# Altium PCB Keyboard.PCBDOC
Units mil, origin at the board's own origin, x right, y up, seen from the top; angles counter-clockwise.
Board outline 6000 x 4000 mil, 2 copper layers (Top Layer, Bottom Layer); 17 components, 8 nets, 40 pads, 0 vias.
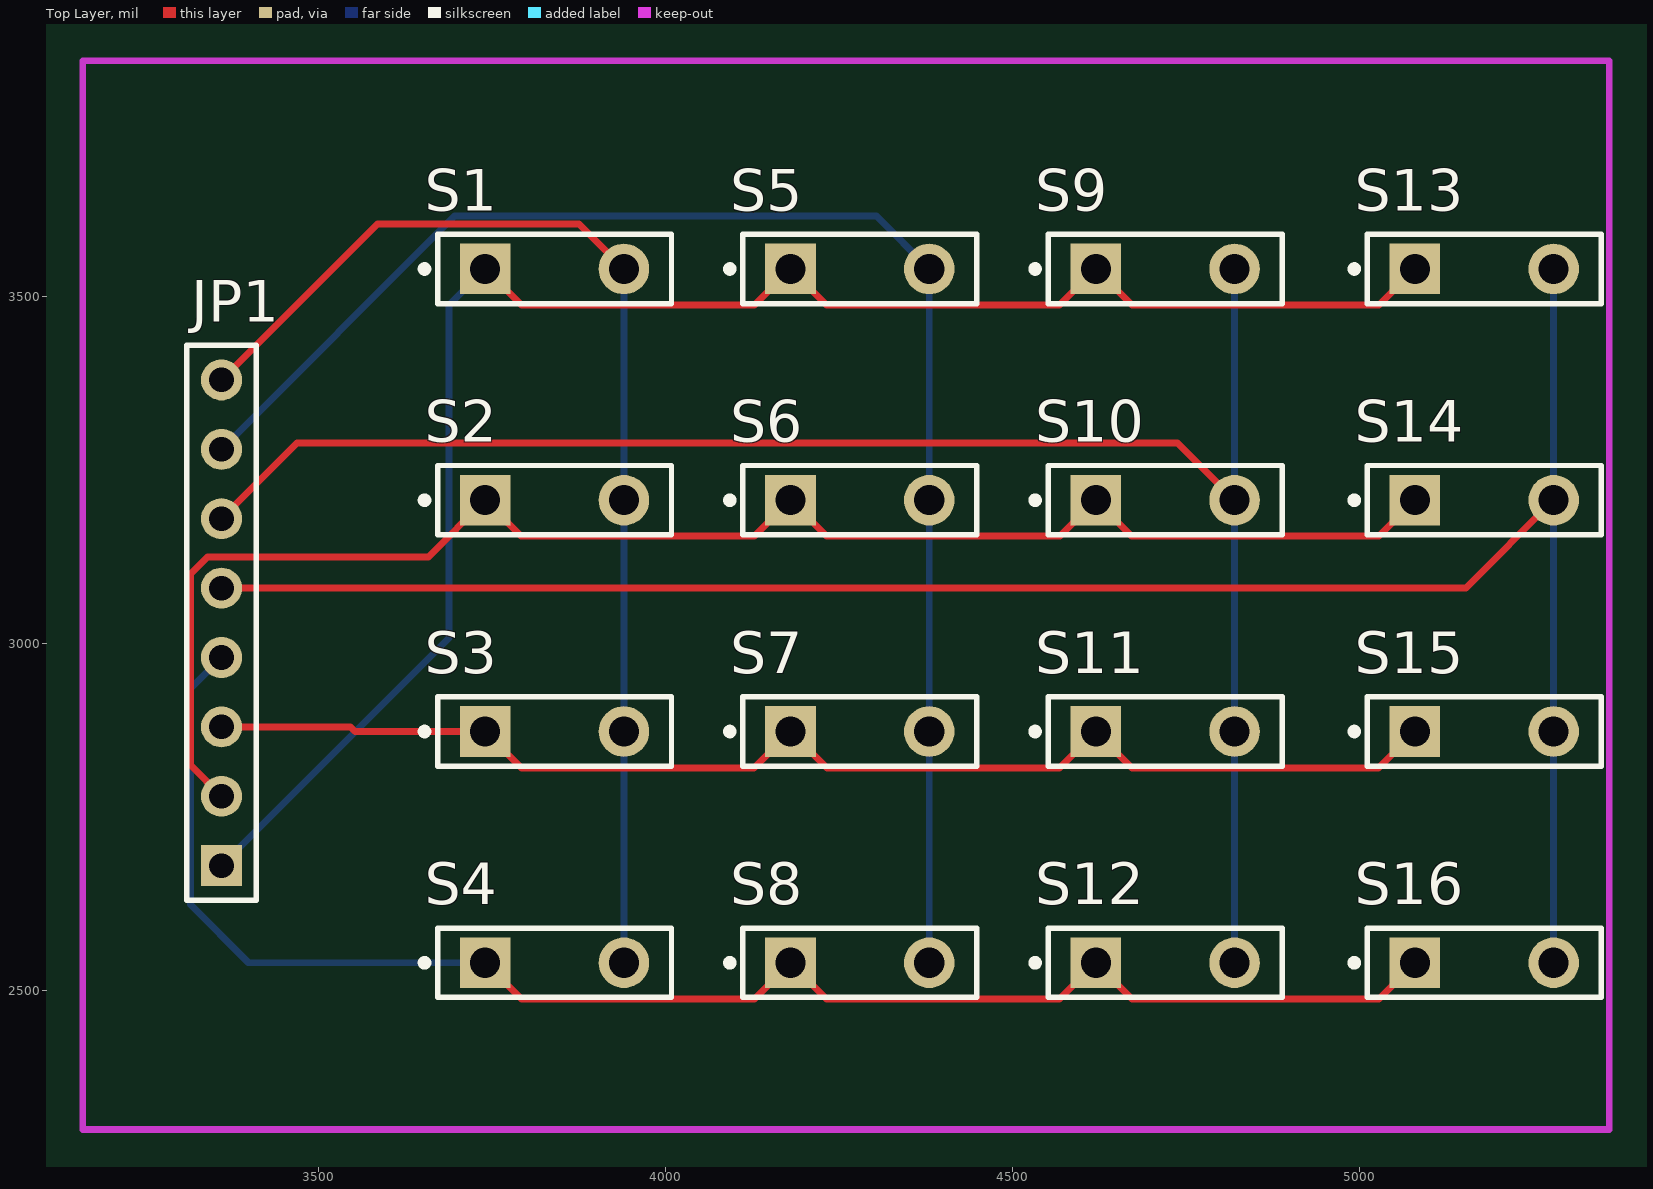
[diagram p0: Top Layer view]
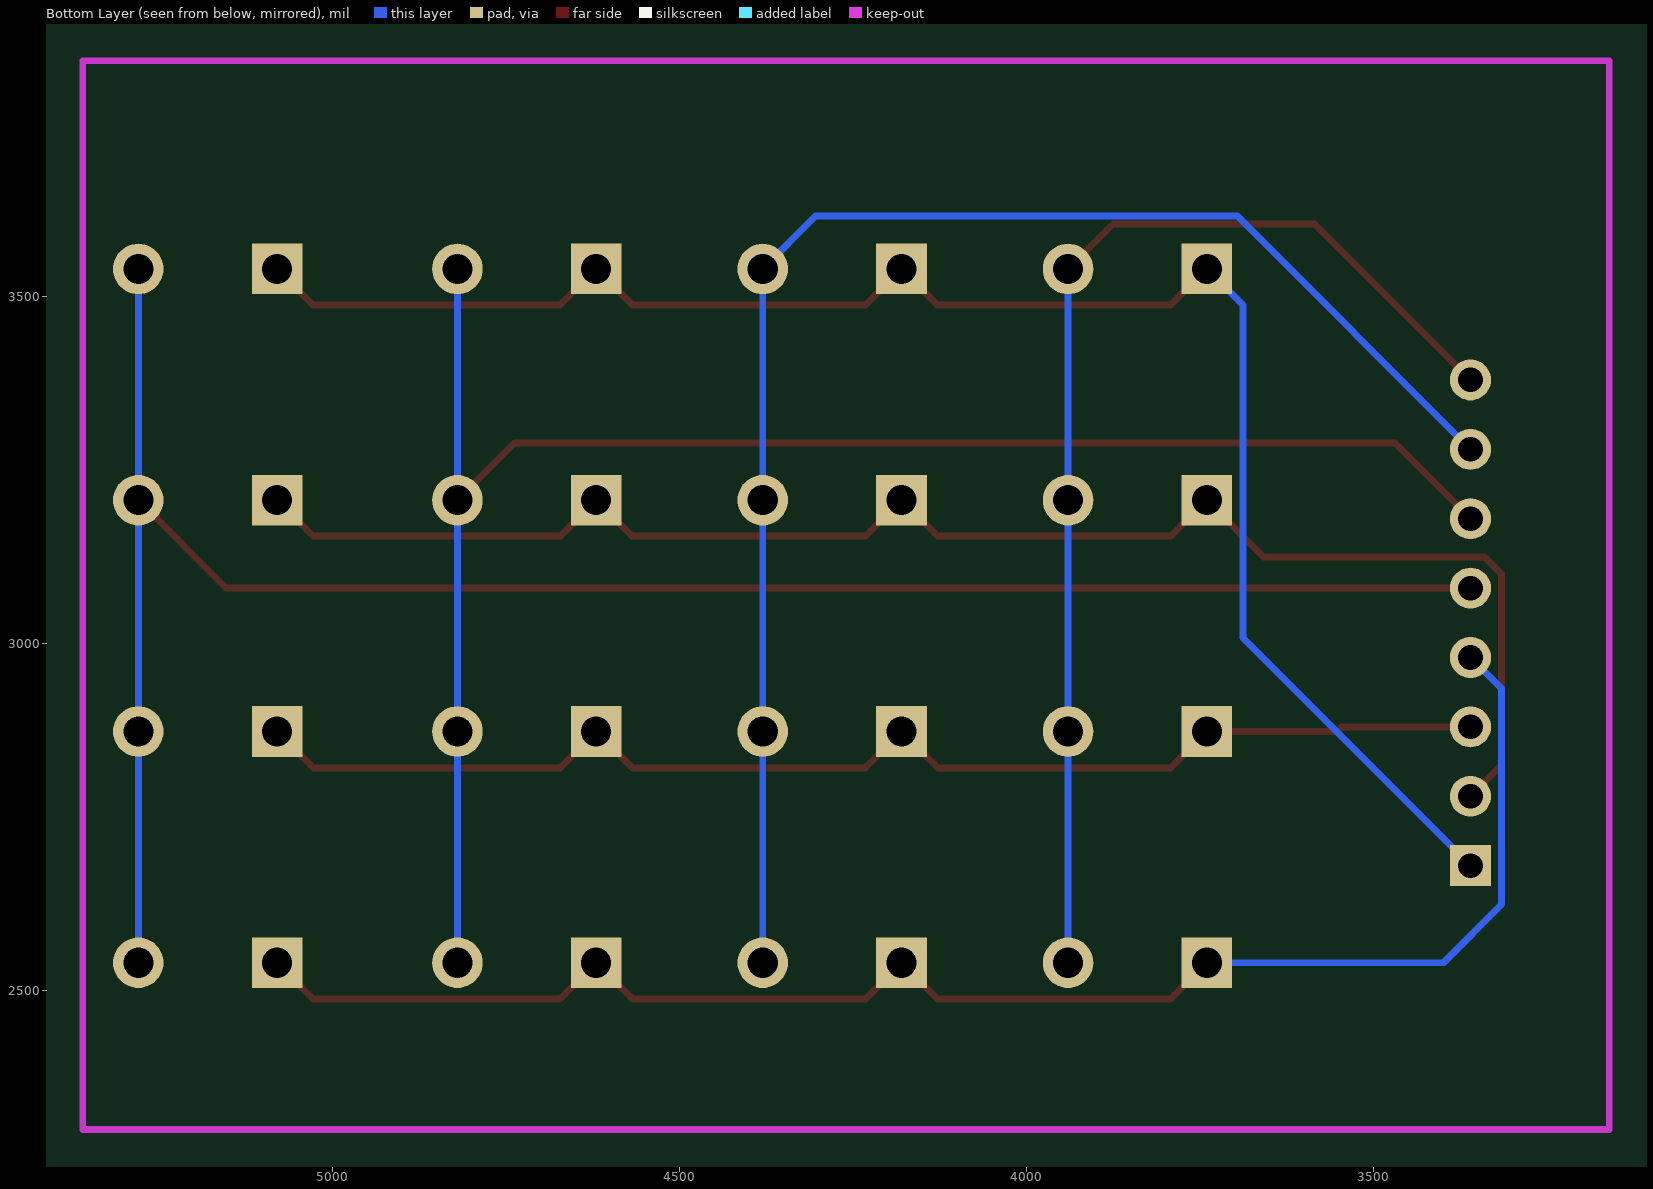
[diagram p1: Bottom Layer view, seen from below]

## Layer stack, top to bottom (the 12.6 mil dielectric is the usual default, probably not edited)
Top Layer: signal copper 1.4
Dielectric: dielectric 12.6, FR-4, Dk 4.8
Bottom Layer: signal copper 1.4

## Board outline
1000,1000 7000,1000 7000,5000 1000,5000

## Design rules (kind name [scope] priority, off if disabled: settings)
Clearance [All] p1: gap=10
ComponentClearance [All] p1: gap=10 collisioncheckmode=0
PolygonConnect [All] p1: connectstyle=Relief reliefconductorwidth=10 reliefentries=4 polygonreliefangle="90 Angle"
RoutingLayers [All] p1: top layer=Horizontal bottom layer=Vertical
RoutingVias [All] p1: holewidth=28 width=50 viastyle="Through Hole" minholewidth=28 minwidth=50 maxholewidth=28 maxwidth=50
SolderMaskExpansion [All] p1: expansion=4
TestPointUsage [All] p1: valid=0 allowmultiple=FALSE
Testpoint [All] p1: side=15 testpointundercomponent=TRUE minsize=40 maxsize=100 preferedsize=60 minholesize=0 maxholesize=40 preferedholesize=32 testpointgrid=1 style=1023 order=1234567890
Width [All] p1: maxlimit=10 minlimit=10 preferedwidth=10
16 further rules are at their usual default settings.

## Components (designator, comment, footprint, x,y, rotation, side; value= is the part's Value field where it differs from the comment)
JP1 "Header 8" HDR1X8 3360,2680 r90 top
S1 "SW-PB" SPST-2 3840,3540 r0 top
S2 "SW-PB" SPST-2 3840,3206.67 r0 top
S3 "SW-PB" SPST-2 3840,2873.33 r0 top
S4 "SW-PB" SPST-2 3840,2540 r0 top
S5 "SW-PB" SPST-2 4280,3540 r0 top
S6 "SW-PB" SPST-2 4280,3206.67 r0 top
S7 "SW-PB" SPST-2 4280,2873.33 r0 top
S8 "SW-PB" SPST-2 4280,2540 r0 top
S9 "SW-PB" SPST-2 4720,3540 r0 top
S10 "SW-PB" SPST-2 4720,3206.67 r0 top
S11 "SW-PB" SPST-2 4720,2873.33 r0 top
S12 "SW-PB" SPST-2 4720,2540 r0 top
S13 "SW-PB" SPST-2 5180,3540 r0 top
S14 "SW-PB" SPST-2 5180,3206.67 r0 top
S15 "SW-PB" SPST-2 5180,2873.33 r0 top
S16 "SW-PB" SPST-2 5180,2540 r0 top

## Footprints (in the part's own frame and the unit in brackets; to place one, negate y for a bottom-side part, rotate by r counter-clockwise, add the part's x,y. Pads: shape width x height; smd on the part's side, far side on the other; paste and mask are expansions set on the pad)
HDR1X8 [mm]
  rect 1.5x1.5 hole 0.9: 1(0,0)
  round 1.5 hole 0.9: 2(2.54,0) 3(5.08,0) 4(7.62,0) 5(10.16,0) 6(12.7,0) 7(15.24,0) 8(17.78,0)
  silkscreen extent -1.27,-1.27 19.05,1.27
SPST-2 [mm]
  rect 1.85x1.85 hole 1.1: 1(-2.54,0)
  round 1.85 hole 1.1: 2(2.54,0)
  silkscreen extent -4.89,-1.27 4.28,1.27

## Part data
JP1: "Header, 8-Pin"
S1 S2 S3 S4 S5 S6 S7 S8 S9 S10 S11 S12 S13 S14 S15 S16: "Switch"

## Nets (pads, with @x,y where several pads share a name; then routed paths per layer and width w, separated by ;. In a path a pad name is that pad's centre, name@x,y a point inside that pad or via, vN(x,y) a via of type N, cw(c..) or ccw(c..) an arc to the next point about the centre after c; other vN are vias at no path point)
NetJP1_1: JP1.1 S1.1 S5.1 S9.1 S13.1 | length 2486.6
  Top Layer w10: S1.1 3792,3488 4128,3488 S5.1 4232,3488 4568,3488 S9.1 4672,3488 5028,3488 S13.1
  Bottom Layer w10: JP1.1 3688,3008 3688,3488 S1.1
NetJP1_2: JP1.2 S2.1 S6.1 S10.1 S14.1 | length 2276.2
  Top Layer w10: JP1.2 3315,2825 3315,3100 3340,3125 3658.33,3125 S2.1 3791.67,3155 4128.33,3155 S6.1 4231.67,3155 4568.33,3155 S10.1 4671.67,3155 5028.33,3155 S14.1
NetJP1_3: JP1.3 S3.1 S7.1 S11.1 S15.1 | length 1852.8
  Top Layer w10: JP1.3 3546,2880 3552.67,2873.33 S3.1 3792.33,2821 4127.67,2821 S7.1 4232.33,2821 4567.67,2821 S11.1 4672.33,2821 5027.67,2821 S15.1
NetJP1_4: JP1.4 S4.1 S8.1 S12.1 S16.1 | length 2303.7
  Top Layer w10: S4.1 3792,2488 4128,2488 S8.1 4232,2488 4568,2488 S12.1 4672,2488 5028,2488 S16.1
  Bottom Layer w10: JP1.4 3315,2935 3315,2624 3399,2540 S4.1
NetJP1_5: JP1.5 S13.2 S14.2 S15.2 S16.2 | length 2972.5
  Top Layer w10: JP1.5 5153.33,3080 S14.2
  Bottom Layer w10: S16.2 S15.2 S14.2 S13.2
NetJP1_6: JP1.6 S9.2 S10.2 S11.2 S12.2 | length 2539.3
  Top Layer w10: JP1.6 3469,3289 4737.67,3289 S10.2
  Bottom Layer w10: S12.2 S11.2 S10.2 S9.2
NetJP1_7: JP1.7 S5.2 S6.2 S7.2 S8.2 | length 2190.7
  Bottom Layer w10: JP1.7 3696,3616 4304,3616 S5.2 S6.2 S7.2 S8.2
NetJP1_8: JP1.8 S1.2 S2.2 S3.2 S4.2 | length 1700.1
  Top Layer w10: JP1.8 3585,3605 3875,3605 S1.2
  Bottom Layer w10: S4.2 S3.2 S2.2 S1.2

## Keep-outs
Keep-Out Layer:
  lines w10: 3160,2300 5360,2300 5360,3840 3160,3840 3160,3720 3160,2300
